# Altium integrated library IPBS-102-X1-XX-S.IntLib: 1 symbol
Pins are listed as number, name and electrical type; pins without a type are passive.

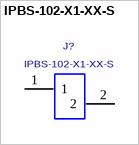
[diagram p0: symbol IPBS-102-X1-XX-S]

## IPBS-102-X1-XX-S
designator J?
0.165" SINGLE ROW SOCKET ASSEMBLY.; MANUFACTURER: SAMTEC
footprint IPBS-102-X1-XX-S
pins: 1, 2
